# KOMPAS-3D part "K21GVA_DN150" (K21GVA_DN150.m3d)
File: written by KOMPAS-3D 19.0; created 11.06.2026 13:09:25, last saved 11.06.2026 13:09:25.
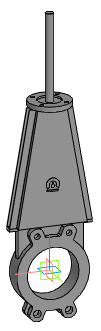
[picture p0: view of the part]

Document properties: Автор: Энергия; Полное имя файла: Z:\3.Личные\kachalov\001_3d для проектировщиков\2.5 Тип_K21GVA. Задвижка\_stp\_stp_K21GVA_DN50-DN1000_с фланцем\K21GVA_DN150.m3d

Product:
- Part/product: K21GVA_DN150

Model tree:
1. Операция без истории:1  (labels: K21GVA_DN150)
